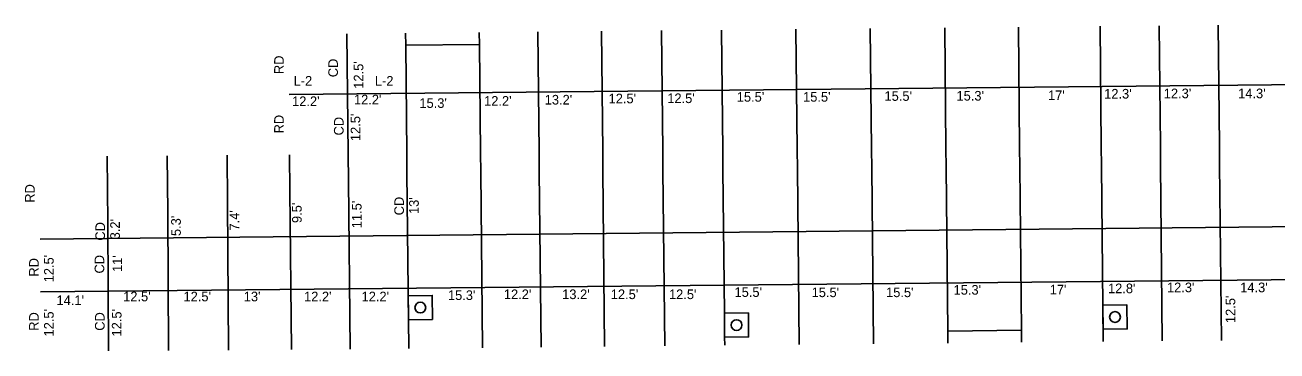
# Model space of a CAD drawing. Extents: x 4995357 to 4999033, y 3881202 to 3881750.
# Drawn here: x 4995357.3 to 4995617.7, y 3881638.8 to 3881706.5 of the extents above; entities that cross this region are included whole.
import ezdxf

# ---------------------------------------------------------------- set-up
doc = ezdxf.new("R2010")
doc.units = 0
for name, color, linetype in [('dsn3DCenterLine', 7, 'Continuous'), ('dsn3DCurbFormgrade', 7, 'Continuous'), ('dsn3DCurbTop', 7, 'Continuous'), ('dsn3DDNC', 7, 'Continuous'), ('dsn3DExistingPvmtBtm', 7, 'Continuous')]:
    doc.layers.add(name, color=color, linetype=linetype)

msp = doc.modelspace()

# ---------------------------------------------------------------- linework, layer by layer
at = {"layer": 'dsn3DCurbFormgrade'}
for p, q in [((4995477.47, 3881680.18), (4995477.22, 3881705.18)), ((4995489.96, 3881680.3), (4995489.71, 3881705.3)), ((4995502.45, 3881680.43), (4995502.2, 3881705.43)), ((4995517.92, 3881680.58), (4995517.67, 3881705.58)), ((4995533.39, 3881680.74), (4995533.14, 3881705.73)), ((4995548.86, 3881680.89), (4995548.61, 3881705.89)), ((4995564.19, 3881681.04), (4995563.94, 3881706.04)), ((4995580.94, 3881706.21), (4995581.19, 3881681.21)), ((4995593.47, 3881681.34), (4995593.22, 3881706.33)), ((4995605.75, 3881681.46), (4995605.5, 3881706.46)), ((4995424.53, 3881679.65), (4995424.28, 3881704.65)), ((4995464.24, 3881680.05), (4995463.99, 3881705.04)), ((4995436.72, 3881679.77), (4995436.49, 3881702.27)), ((4995452.05, 3881679.92), (4995451.82, 3881702.42)), ((4995517.96, 3881676.58), (4995518.32, 3881640.08)), ((4995533.43, 3881676.74), (4995533.79, 3881640.24)), ((4995548.9, 3881676.89), (4995549.24, 3881642.89)), ((4995564.23, 3881677.04), (4995564.57, 3881643.05)), ((4995581.23, 3881677.21), (4995581.59, 3881640.71)), ((4995593.51, 3881677.34), (4995593.87, 3881640.84)), ((4995605.79, 3881677.46), (4995606.16, 3881640.96)), ((4995424.58, 3881674.19), (4995424.93, 3881639.15)), ((4995436.76, 3881675.77), (4995437.12, 3881639.27)), ((4995452.09, 3881675.92), (4995452.45, 3881639.43)), ((4995464.28, 3881676.05), (4995464.64, 3881639.55)), ((4995477.87, 3881639.68), (4995477.51, 3881676.18)), ((4995490, 3881676.3), (4995490.36, 3881639.8)), ((4995502.49, 3881676.43), (4995502.78, 3881646.61)), ((4995412.41, 3881672.05), (4995412.74, 3881639.03)), ((4995399.66, 3881638.94), (4995399.44, 3881669.76)), ((4995387.18, 3881638.85), (4995386.98, 3881667.56)), ((4995374.68, 3881638.76), (4995374.5, 3881665.36)), ((4995502.83, 3881641.61), (4995502.85, 3881639.93))]:
    msp.add_line(p, q, dxfattribs=at)
at = {"layer": 'dsn3DCurbTop'}
for p, q in [((4995374.36, 3881679.21), (4995374.5, 3881665.36)), ((4995386.86, 3881679.31), (4995386.98, 3881667.56)), ((4995399.35, 3881679.42), (4995399.44, 3881669.76)), ((4995412.34, 3881679.53), (4995412.41, 3881672.05)), ((4995424.53, 3881679.65), (4995424.58, 3881674.19)), ((4995436.72, 3881679.77), (4995436.76, 3881675.77)), ((4995452.05, 3881679.92), (4995452.09, 3881675.92)), ((4995464.24, 3881680.05), (4995464.28, 3881676.05)), ((4995477.51, 3881676.18), (4995477.47, 3881680.18)), ((4995490, 3881676.3), (4995489.96, 3881680.3)), ((4995502.49, 3881676.43), (4995502.45, 3881680.43)), ((4995517.96, 3881676.58), (4995517.92, 3881680.58)), ((4995533.43, 3881676.74), (4995533.39, 3881680.74)), ((4995548.9, 3881676.89), (4995548.86, 3881680.89)), ((4995564.23, 3881677.04), (4995564.19, 3881681.04)), ((4995581.23, 3881677.21), (4995581.19, 3881681.21)), ((4995593.47, 3881681.34), (4995593.51, 3881677.34)), ((4995605.75, 3881681.46), (4995605.79, 3881677.46))]:
    msp.add_line(p, q, dxfattribs=at)
at = {"layer": 'dsn3DDNC'}
for p, q in [((4995412.22, 3881692.03), (4995693.02, 3881694.83)), ((4995360.43, 3881662.01), (4995693.14, 3881665.33)), ((4995360.54, 3881651.01), (4995693.19, 3881654.33))]:
    msp.add_line(p, q, dxfattribs=at)
at = {"layer": 'dsn3DExistingPvmtBtm'}
for points in [[(4995436.47, 3881704.77), (4995436.49, 3881702.27), (4995451.82, 3881702.42), (4995451.8, 3881704.92)], [(4995549.26, 3881640.39), (4995549.24, 3881642.89), (4995564.57, 3881643.05), (4995564.59, 3881640.55)]]:
    msp.add_lwpolyline(points, dxfattribs=at)
for points in [[(4995437.01, 3881650.24), (4995442.01, 3881650.29), (4995442.06, 3881645.3), (4995437.06, 3881645.25)], [(4995581.52, 3881648.28), (4995586.52, 3881648.33), (4995586.57, 3881643.33), (4995581.57, 3881643.28)], [(4995502.78, 3881646.61), (4995507.78, 3881646.66), (4995507.83, 3881641.66), (4995502.83, 3881641.61)]]:
    msp.add_lwpolyline(points, close=True, dxfattribs=at)
for centre in [(4995439.54, 3881647.77), (4995584.04, 3881645.81), (4995505.31, 3881644.13)]:
    msp.add_circle(centre, 1.12, dxfattribs=at)

# ---------------------------------------------------------------- texts
at = {"layer": 'dsn3DCenterLine'}
for s, p in [('RD', (4995411.13, 3881696.27)), ('CD', (4995422.39, 3881695.62)), ("12.5'", (4995427.69, 3881693.23)), ('RD', (4995411.13, 3881683.95)), ('CD', (4995423.57, 3881683.52)), ("12.5'", (4995427.04, 3881682.35)), ('RD', (4995359.31, 3881669.55)), ("9.5'", (4995414.85, 3881665.33)), ("11.5'", (4995427.31, 3881664.25)), ('CD', (4995436.12, 3881666.93)), ("13'", (4995439.21, 3881667.2)), ("5.3'", (4995389.71, 3881662.62)), ("7.4'", (4995401.86, 3881663.78)), ('CD', (4995373.94, 3881661.67)), ("3.2'", (4995377.03, 3881661.94)), ("12.5'", (4995363.27, 3881653.01)), ('CD', (4995373.78, 3881654.84)), ("11'", (4995377.51, 3881655.16)), ('RD', (4995360.15, 3881654.2)), ("12.5'", (4995609.06, 3881644.54)), ('RD', (4995360.15, 3881642.95)), ("12.5'", (4995363.27, 3881641.76)), ('CD', (4995373.86, 3881642.95)), ("12.5'", (4995377.37, 3881641.76))]:
    msp.add_text(s, height=2, rotation=90, dxfattribs=at).set_placement(p)
for s, p in [('L-2', (4995413.17, 3881693.87)), ('L-2', (4995430.08, 3881693.87)), ("12.5'", (4995478.69, 3881690.2)), ("12.5'", (4995490.9, 3881690.25)), ("15.5'", (4995505.36, 3881690.54)), ("15.5'", (4995519.15, 3881690.54)), ("15.5'", (4995536.09, 3881690.72)), ("15.3'", (4995551.06, 3881690.77)), ("17'", (4995570.1, 3881690.87)), ("12.3'", (4995581.78, 3881691.19)), ("12.3'", (4995594.18, 3881691.26)), ("14.3'", (4995609.65, 3881691.26)), ("12.2'", (4995412.86, 3881689.64)), ("12.2'", (4995425.73, 3881689.98)), ("15.3'", (4995439.34, 3881689.25)), ("12.2'", (4995452.8, 3881689.71)), ("13.2'", (4995465.41, 3881689.95)), ("12.5'", (4995377.72, 3881649.07)), ("12.5'", (4995390.27, 3881649.07)), ("13'", (4995402.81, 3881649.07)), ("12.2'", (4995415.35, 3881649.07)), ("12.2'", (4995427.31, 3881649.07)), ("15.3'", (4995445.28, 3881649.34)), ("12.2'", (4995456.91, 3881649.53)), ("13.2'", (4995469.04, 3881649.53)), ("12.5'", (4995479.15, 3881649.53)), ("12.5'", (4995491.26, 3881649.53)), ("15.5'", (4995504.89, 3881649.98)), ("15.5'", (4995520.93, 3881649.94)), ("15.5'", (4995536.41, 3881649.94)), ("15.3'", (4995550.46, 3881650.45)), ("17'", (4995570.45, 3881650.5)), ("12.8'", (4995582.58, 3881650.76)), ("12.3'", (4995594.85, 3881650.96)), ("14.3'", (4995610.08, 3881650.96)), ("14.1'", (4995363.85, 3881648.28))]:
    msp.add_text(s, height=2, dxfattribs=at).set_placement(p)

doc.saveas('drawing.dxf')
